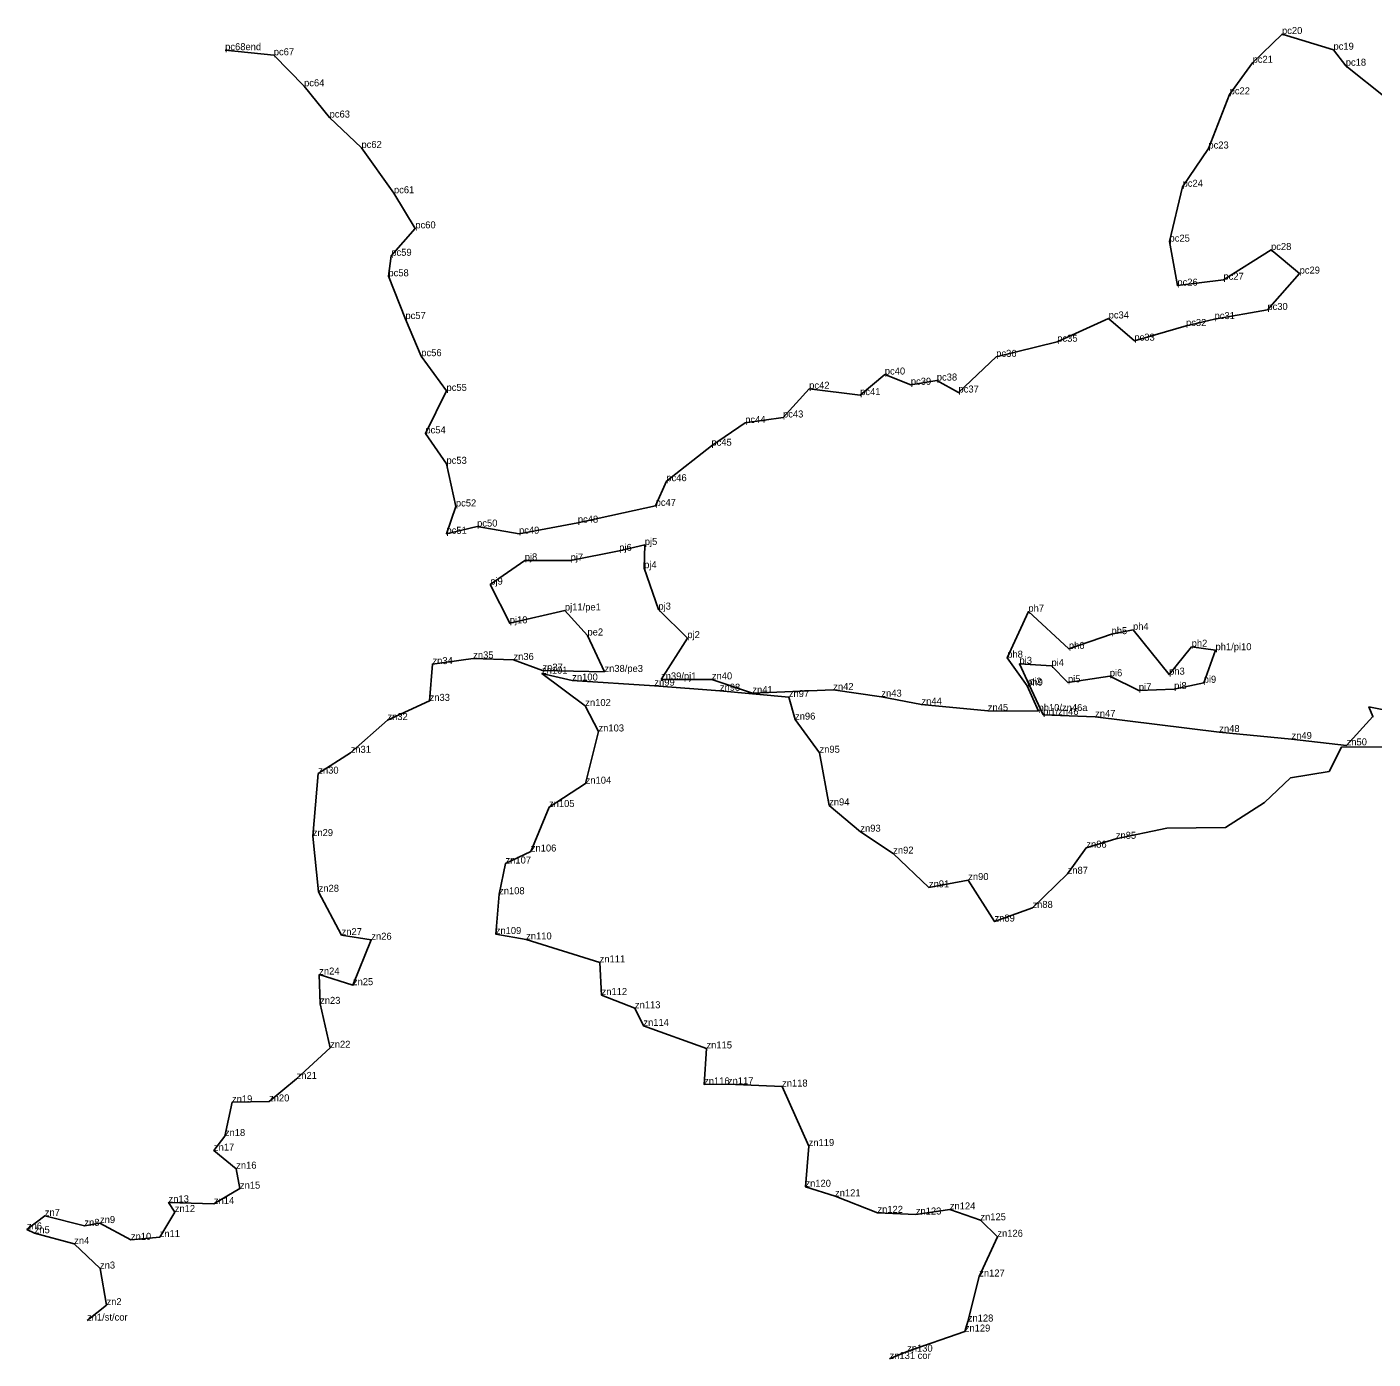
# Model space of a CAD drawing. Extents: x 2072529 to 2267990, y 436423 to 470008.
# Drawn here: x 2230236 to 2231389, y 437912 to 439053 of the extents above; entities that cross this region are included whole.
import ezdxf

# ---------------------------------------------------------------- set-up
doc = ezdxf.new("R2010")
doc.units = 0
doc.layers.add('Level 3', color=7, linetype='Continuous')
doc.layers.add('Old_Level_52', color=7, linetype='Continuous')

msp = doc.modelspace()

# ---------------------------------------------------------------- linework, layer by layer
at = {"layer": 'Level 3'}
for p, q in [((2231310.939, 439047.151), (2231310.939, 439047.151)), ((2230405.831, 439033.328), (2230405.831, 439033.328)), ((2230447.46, 439028.971), (2230447.46, 439028.971)), ((2231355.02, 439033.712), (2231355.02, 439033.712)), ((2231285.762, 439022.487), (2231285.762, 439022.487)), ((2231365.533, 439019.989), (2231365.533, 439019.989)), ((2230473.411, 439002.406), (2230473.411, 439002.406)), ((2231266.087, 438995.494), (2231266.087, 438995.494)), ((2230495.293, 438975.627), (2230495.293, 438975.627)), ((2230522.567, 438949.582), (2230522.567, 438949.582)), ((2231247.897, 438949.098), (2231247.897, 438949.098)), ((2231225.791, 438916.331), (2231225.791, 438916.331)), ((2230550.391, 438910.797), (2230550.391, 438910.797)), ((2230568.692, 438880.673), (2230568.692, 438880.673)), ((2231214.611, 438869.338), (2231214.611, 438869.338)), ((2230548.133, 438857.217), (2230548.133, 438857.217)), ((2231301.537, 438862.206), (2231301.537, 438862.206)), ((2230545.636, 438839.663), (2230545.636, 438839.663)), ((2231221.32, 438831.672), (2231221.32, 438831.672)), ((2231260.743, 438836.686), (2231260.743, 438836.686)), ((2231326.024, 438841.986), (2231326.024, 438841.986)), ((2231298.42, 438810.803), (2231298.42, 438810.803)), ((2230560.209, 438803.028), (2230560.209, 438803.028)), ((2231162.477, 438803.55), (2231162.477, 438803.55)), ((2231228.715, 438797.116), (2231228.715, 438797.116)), ((2231253.174, 438803.008), (2231253.174, 438803.008)), ((2231184.503, 438784.523), (2231184.503, 438784.523)), ((2231118.455, 438783.598), (2231118.455, 438783.598)), ((2230573.781, 438771.245), (2230573.781, 438771.245)), ((2231066.183, 438770.672), (2231066.183, 438770.672)), ((2230970.771, 438755.527), (2230970.771, 438755.527)), ((2231015.31, 438750.373), (2231015.31, 438750.373)), ((2230595.395, 438741.485), (2230595.395, 438741.485)), ((2230906.001, 438743.321), (2230906.001, 438743.321)), ((2230993.066, 438746.762), (2230993.066, 438746.762)), ((2231033.873, 438740.121), (2231033.873, 438740.121)), ((2230949.664, 438737.874), (2230949.664, 438737.874)), ((2230883.589, 438718.737), (2230883.589, 438718.737)), ((2230577.298, 438705.125), (2230577.298, 438705.125)), ((2230851.215, 438714.046), (2230851.215, 438714.046)), ((2230822.259, 438694.53), (2230822.259, 438694.53)), ((2230595.378, 438679.047), (2230595.378, 438679.047)), ((2230783.671, 438664.176), (2230783.671, 438664.176)), ((2230603.451, 438642.538), (2230603.451, 438642.538)), ((2230774.498, 438643.053), (2230774.498, 438643.053)), ((2230621.592, 438625.293), (2230621.592, 438625.293)), ((2230707.866, 438628.604), (2230707.866, 438628.604)), ((2230595.38, 438619.106), (2230595.38, 438619.106)), ((2230657.511, 438619.21), (2230657.511, 438619.21)), ((2230743.307, 438604.473), (2230743.307, 438604.473)), ((2230765.194, 438609.563), (2230765.194, 438609.563)), ((2230662.389, 438596.38), (2230662.389, 438596.38)), ((2230701.659, 438596.151), (2230701.659, 438596.151)), ((2230764.662, 438589.686), (2230764.662, 438589.686)), ((2230632.844, 438575.589), (2230632.844, 438575.589)), ((2230776.862, 438554.192), (2230776.862, 438554.192)), ((2230649.553, 438542.437), (2230649.553, 438542.437)), ((2230696.786, 438553.431), (2230696.786, 438553.431)), ((2231093.706, 438552.451), (2231093.706, 438552.451)), ((2230716.124, 438532.013), (2230716.124, 438532.013)), ((2231164.949, 438533.178), (2231164.949, 438533.178)), ((2231183.359, 438536.86), (2231183.359, 438536.86)), ((2230801.646, 438529.778), (2230801.646, 438529.778)), ((2231128.407, 438520.53), (2231128.407, 438520.53)), ((2231233.56, 438522.426), (2231233.56, 438522.426)), ((2231253.979, 438519.434), (2231253.979, 438519.434)), ((2230618.25, 438512.377), (2230618.25, 438512.377)), ((2230652.739, 438511.054), (2230652.739, 438511.054)), ((2231075.618, 438513.001), (2231075.618, 438513.001)), ((2230583.339, 438507.503), (2230583.339, 438507.503)), ((2230677.154, 438499.344), (2230677.154, 438499.344)), ((2230677.577, 438501.915), (2230677.577, 438501.915)), ((2230730.635, 438500.82), (2230730.635, 438500.82)), ((2231086.1, 438507.739), (2231086.1, 438507.739)), ((2231113.506, 438505.973), (2231113.506, 438505.973)), ((2231163.43, 438497.127), (2231163.43, 438497.127)), ((2231214.241, 438498.484), (2231214.241, 438498.484)), ((2230703.077, 438493.453), (2230703.077, 438493.453)), ((2230773.413, 438489.04), (2230773.413, 438489.04)), ((2230779.099, 438494.344), (2230779.099, 438494.344)), ((2230822.636, 438494.431), (2230822.636, 438494.431)), ((2230926.6, 438485.362), (2230926.6, 438485.362)), ((2231092.731, 438489.038), (2231092.731, 438489.038)), ((2231094.274, 438489.856), (2231094.274, 438489.856)), ((2231127.606, 438491.863), (2231127.606, 438491.863)), ((2231188.302, 438484.985), (2231188.302, 438484.985)), ((2231218.577, 438486.154), (2231218.577, 438486.154)), ((2231243.846, 438491.506), (2231243.846, 438491.506)), ((2230580.917, 438476.025), (2230580.917, 438476.025)), ((2230829.511, 438484.694), (2230829.511, 438484.694)), ((2230857.331, 438482.66), (2230857.331, 438482.66)), ((2230888.561, 438479.289), (2230888.561, 438479.289)), ((2230967.821, 438479.621), (2230967.821, 438479.621)), ((2230714.241, 438471.668), (2230714.241, 438471.668)), ((2231002.165, 438472.775), (2231002.165, 438472.775)), ((2231058.976, 438467.467), (2231058.976, 438467.467)), ((2231102.432, 438467.32), (2231102.432, 438467.32)), ((2231106.33, 438463.945), (2231106.33, 438463.945)), ((2231150.873, 438462.26), (2231150.873, 438462.26)), ((2231388.763, 438462.605), (2231388.763, 438462.605)), ((2230544.811, 438459.575), (2230544.811, 438459.575)), ((2230893.868, 438459.965), (2230893.868, 438459.965)), ((2230725.563, 438449.815), (2230725.563, 438449.815)), ((2231257.201, 438449.319), (2231257.201, 438449.319)), ((2231319.092, 438443.334), (2231319.092, 438443.334)), ((2230513.299, 438431.528), (2230513.299, 438431.528)), ((2230914.834, 438431.593), (2230914.834, 438431.593)), ((2231366.264, 438437.874), (2231366.264, 438437.874)), ((2230485.56, 438413.683), (2230485.56, 438413.683)), ((2230714.565, 438405.115), (2230714.565, 438405.115)), ((2230683.171, 438385.102), (2230683.171, 438385.102)), ((2230923.078, 438386.475), (2230923.078, 438386.475)), ((2230480.817, 438360.197), (2230480.817, 438360.197)), ((2230949.818, 438363.989), (2230949.818, 438363.989)), ((2230667.597, 438346.988), (2230667.597, 438346.988)), ((2231143.341, 438350.29), (2231143.341, 438350.29)), ((2231168.569, 438357.879), (2231168.569, 438357.879)), ((2230645.912, 438336.705), (2230645.912, 438336.705)), ((2230977.955, 438345.227), (2230977.955, 438345.227)), ((2231127.348, 438327.905), (2231127.348, 438327.905)), ((2230485.895, 438312.516), (2230485.895, 438312.516)), ((2231008.552, 438316.283), (2231008.552, 438316.283)), ((2231042.176, 438322.552), (2231042.176, 438322.552)), ((2230640.408, 438310.426), (2230640.408, 438310.426)), ((2231097.19, 438298.687), (2231097.19, 438298.687)), ((2231064.708, 438287.03), (2231064.708, 438287.03)), ((2230505.549, 438275.391), (2230505.549, 438275.391)), ((2230531.006, 438271.455), (2230531.006, 438271.455)), ((2230637.561, 438276.332), (2230637.561, 438276.332)), ((2230663.58, 438271.657), (2230663.58, 438271.657)), ((2230726.563, 438252.057), (2230726.563, 438252.057)), ((2230486.366, 438241.632), (2230486.366, 438241.632)), ((2230515.222, 438232.535), (2230515.222, 438232.535)), ((2230728.203, 438224.109), (2230728.203, 438224.109)), ((2230487.132, 438216.516), (2230487.132, 438216.516)), ((2230756.759, 438212.749), (2230756.759, 438212.749)), ((2230763.994, 438197.68), (2230763.994, 438197.68)), ((2230495.691, 438178.911), (2230495.691, 438178.911)), ((2230818.043, 438178.348), (2230818.043, 438178.348)), ((2230467.018, 438152.256), (2230467.018, 438152.256)), ((2230815.968, 438147.547), (2230815.968, 438147.547)), ((2230836.377, 438147.671), (2230836.377, 438147.671)), ((2230882.768, 438145.682), (2230882.768, 438145.682)), ((2230411.69, 438132.217), (2230411.69, 438132.217)), ((2230443.396, 438132.954), (2230443.396, 438132.954)), ((2230405.568, 438103.302), (2230405.568, 438103.302)), ((2230905.558, 438094.768), (2230905.558, 438094.768)), ((2230396.199, 438090.877), (2230396.199, 438090.877)), ((2230415.261, 438075.336), (2230415.261, 438075.336)), ((2230418.466, 438058.268), (2230418.466, 438058.268)), ((2230902.75, 438059.87), (2230902.75, 438059.87)), ((2230928.135, 438051.731), (2230928.135, 438051.731)), ((2230357.359, 438046.533), (2230357.359, 438046.533)), ((2230362.647, 438038.259), (2230362.647, 438038.259)), ((2230396.169, 438045.119), (2230396.169, 438045.119)), ((2230964.443, 438037.537), (2230964.443, 438037.537)), ((2230997.313, 438036.112), (2230997.313, 438036.112)), ((2231026.441, 438040.43), (2231026.441, 438040.43)), ((2230251.357, 438034.955), (2230251.357, 438034.955)), ((2230285.253, 438026.391), (2230285.253, 438026.391)), ((2230298.62, 438028.753), (2230298.62, 438028.753)), ((2231052.615, 438031.201), (2231052.615, 438031.201)), ((2230236.05, 438023.325), (2230236.05, 438023.325)), ((2230242.646, 438020.093), (2230242.646, 438020.093)), ((2230325.096, 438014.422), (2230325.096, 438014.422)), ((2230349.737, 438016.733), (2230349.737, 438016.733)), ((2231067.164, 438017.056), (2231067.164, 438017.056)), ((2230276.544, 438010.892), (2230276.544, 438010.892)), ((2230298.636, 437989.826), (2230298.636, 437989.826)), ((2231051.606, 437983.008), (2231051.606, 437983.008)), ((2230304.22, 437958.48), (2230304.22, 437958.48)), ((2230287.505, 437945.265), (2230287.505, 437945.265)), ((2231041.838, 437944.457), (2231041.838, 437944.457)), ((2231039.241, 437935.876), (2231039.241, 437935.876)), ((2230974.811, 437912.378), (2230974.811, 437912.378)), ((2230989.871, 437918.676), (2230989.871, 437918.676))]:
    msp.add_line(p, q, dxfattribs=at)
at = {"layer": 'Old_Level_52'}
for points in [[(2231400.682, 438991.914), (2231365.533, 439019.989), (2231355.02, 439033.712), (2231310.939, 439047.151), (2231285.762, 439022.487), (2231266.087, 438995.494), (2231247.897, 438949.098), (2231225.791, 438916.331), (2231214.611, 438869.338), (2231221.32, 438831.672), (2231260.743, 438836.686), (2231301.537, 438862.206), (2231326.024, 438841.986), (2231298.42, 438810.803), (2231253.174, 438803.008), (2231228.715, 438797.116), (2231184.503, 438784.523), (2231162.477, 438803.55), (2231118.455, 438783.598), (2231066.183, 438770.672), (2231033.873, 438740.121), (2231015.31, 438750.373), (2230993.066, 438746.762), (2230970.771, 438755.527), (2230949.664, 438737.874), (2230906.001, 438743.321), (2230883.589, 438718.737), (2230851.215, 438714.046), (2230822.259, 438694.53), (2230783.671, 438664.176), (2230774.498, 438643.053), (2230707.866, 438628.604), (2230657.511, 438619.21), (2230621.592, 438625.293), (2230595.38, 438619.106), (2230603.451, 438642.538), (2230595.378, 438679.047), (2230577.298, 438705.125), (2230595.395, 438741.485), (2230573.781, 438771.245), (2230560.209, 438803.028), (2230545.636, 438839.663), (2230548.133, 438857.217), (2230568.692, 438880.673), (2230550.391, 438910.797), (2230522.567, 438949.582), (2230495.293, 438975.627), (2230473.411, 439002.406), (2230447.46, 439028.971), (2230405.831, 439033.328)], [(2230779.099, 438494.344), (2230801.646, 438529.778), (2230776.862, 438554.192), (2230764.662, 438589.686), (2230765.194, 438609.563), (2230743.307, 438604.473), (2230701.659, 438596.151), (2230662.389, 438596.38), (2230632.844, 438575.589), (2230649.553, 438542.437), (2230696.786, 438553.431), (2230716.124, 438532.013), (2230730.635, 438500.82)], [(2231106.33, 438463.945), (2231094.273, 438489.856), (2231086.1, 438507.739), (2231113.506, 438505.973), (2231127.606, 438491.863), (2231163.43, 438497.127), (2231188.302, 438484.985), (2231218.577, 438486.154), (2231243.846, 438491.506), (2231253.979, 438519.434), (2231233.56, 438522.426), (2231214.241, 438498.484), (2231183.359, 438536.86), (2231164.949, 438533.178), (2231128.407, 438520.53), (2231093.706, 438552.451), (2231075.618, 438513.001), (2231092.73, 438489.038), (2231102.432, 438467.32)], [(2230287.505, 437945.265), (2230304.22, 437958.48), (2230298.636, 437989.826), (2230276.544, 438010.892), (2230242.646, 438020.093), (2230236.05, 438023.325), (2230251.357, 438034.955), (2230285.253, 438026.391), (2230298.62, 438028.753), (2230325.096, 438014.422), (2230349.737, 438016.733), (2230362.647, 438038.259), (2230357.359, 438046.533), (2230396.169, 438045.119), (2230418.466, 438058.268), (2230415.261, 438075.336), (2230396.199, 438090.877), (2230405.568, 438103.302), (2230411.69, 438132.217), (2230443.396, 438132.954), (2230467.018, 438152.256), (2230495.691, 438178.911), (2230487.132, 438216.516), (2230486.366, 438241.632), (2230515.222, 438232.535), (2230531.006, 438271.455), (2230505.549, 438275.391), (2230485.895, 438312.516), (2230480.817, 438360.197), (2230485.56, 438413.683), (2230513.299, 438431.528), (2230544.811, 438459.575), (2230580.917, 438476.025), (2230583.339, 438507.503), (2230618.25, 438512.377), (2230652.739, 438511.054), (2230677.577, 438501.915), (2230730.635, 438500.82)], [(2230773.413, 438489.04), (2230703.077, 438493.453), (2230677.154, 438499.344), (2230714.241, 438471.668), (2230725.563, 438449.815), (2230714.565, 438405.115), (2230683.171, 438385.102), (2230667.597, 438346.988), (2230645.912, 438336.705), (2230640.408, 438310.426), (2230637.561, 438276.332), (2230663.58, 438271.657), (2230726.563, 438252.057), (2230728.203, 438224.109), (2230756.759, 438212.749), (2230763.994, 438197.68), (2230818.043, 438178.348), (2230815.968, 438147.547), (2230836.377, 438147.671), (2230882.768, 438145.682), (2230905.558, 438094.768), (2230902.75, 438059.87), (2230928.135, 438051.731), (2230964.443, 438037.537), (2230997.313, 438036.112), (2231026.441, 438040.43), (2231052.615, 438031.201), (2231067.164, 438017.056), (2231051.606, 437983.008), (2231041.838, 437944.457), (2231039.241, 437935.876), (2230989.871, 437918.676), (2230974.811, 437912.378)], [(2231168.569, 438357.879), (2231143.341, 438350.29), (2231127.348, 438327.905), (2231097.19, 438298.687), (2231064.708, 438287.03), (2231042.176, 438322.552), (2231008.552, 438316.283), (2230977.955, 438345.227), (2230949.818, 438363.989), (2230923.078, 438386.475), (2230914.834, 438431.593), (2230893.868, 438459.965), (2230888.532, 438479.288), (2230829.511, 438484.694), (2230773.413, 438489.04)], [(2230779.099, 438494.344), (2230822.636, 438494.431), (2230857.331, 438482.66), (2230926.6, 438485.362), (2230967.821, 438479.621), (2231002.165, 438472.775), (2231058.976, 438467.467), (2231102.432, 438467.32)], [(2231106.33, 438463.945), (2231150.873, 438462.26), (2231257.201, 438449.319), (2231319.092, 438443.334), (2231366.264, 438437.874), (2231388.763, 438462.605)], [(2231407.746, 438466.318), (2231385.301, 438470.85), (2231388.763, 438462.605), (2231389.195, 438462.745)], [(2231168.569, 438357.879), (2231212.348, 438367.123), (2231262.574, 438367.521), (2231295.835, 438388.926), (2231318.259, 438409.984), (2231351.285, 438415.525), (2231362.005, 438436.45), (2231401.873, 438436.73)]]:
    msp.add_lwpolyline(points, dxfattribs=at)

# ---------------------------------------------------------------- texts
for s, p in [('pc20', (2231310.939, 439047.151)), ('pc68end', (2230405.831, 439033.328)), ('pc19', (2231355.02, 439033.712)), ('pc67', (2230447.46, 439028.971)), ('pc21', (2231285.762, 439022.487)), ('pc18', (2231365.533, 439019.989)), ('pc64', (2230473.411, 439002.406)), ('pc22', (2231266.087, 438995.494)), ('pc63', (2230495.293, 438975.627)), ('pc62', (2230522.567, 438949.582)), ('pc23', (2231247.897, 438949.098)), ('pc61', (2230550.391, 438910.797)), ('pc24', (2231225.791, 438916.331)), ('pc60', (2230568.692, 438880.673)), ('pc25', (2231214.611, 438869.338)), ('pc28', (2231301.537, 438862.206)), ('pc59', (2230548.133, 438857.217)), ('pc58', (2230545.636, 438839.663)), ('pc27', (2231260.743, 438836.686)), ('pc29', (2231326.024, 438841.986)), ('pc26', (2231221.32, 438831.672)), ('pc57', (2230560.209, 438803.028)), ('pc34', (2231162.477, 438803.55)), ('pc31', (2231253.174, 438803.008)), ('pc30', (2231298.42, 438810.803)), ('pc32', (2231228.715, 438797.116)), ('pc35', (2231118.455, 438783.598)), ('pc33', (2231184.503, 438784.523)), ('pc56', (2230573.781, 438771.245)), ('pc36', (2231066.183, 438770.672)), ('pc40', (2230970.771, 438755.527)), ('pc39', (2230993.066, 438746.762)), ('pc38', (2231015.31, 438750.373)), ('pc55', (2230595.395, 438741.485)), ('pc42', (2230906.001, 438743.321)), ('pc41', (2230949.664, 438737.874)), ('pc37', (2231033.873, 438740.121)), ('pc44', (2230851.215, 438714.046)), ('pc43', (2230883.589, 438718.737)), ('pc54', (2230577.298, 438705.125)), ('pc45', (2230822.259, 438694.53)), ('pc53', (2230595.378, 438679.047)), ('pc46', (2230783.671, 438664.176)), ('pc52', (2230603.451, 438642.538)), ('pc47', (2230774.498, 438643.053)), ('pc48', (2230707.866, 438628.604)), ('pc51', (2230595.38, 438619.106)), ('pc50', (2230621.592, 438625.293)), ('pc49', (2230657.511, 438619.21)), ('pj5', (2230765.194, 438609.563)), ('pj8', (2230662.389, 438596.38)), ('pj7', (2230701.659, 438596.151)), ('pj6', (2230743.307, 438604.473)), ('pj4', (2230764.662, 438589.686)), ('pj9', (2230632.844, 438575.589)), ('pj11/pe1', (2230696.786, 438553.431)), ('pj3', (2230776.862, 438554.192)), ('ph7', (2231093.706, 438552.451)), ('pj10', (2230649.553, 438542.437)), ('ph4', (2231183.359, 438536.86)), ('pe2', (2230716.124, 438532.013)), ('pj2', (2230801.646, 438529.778)), ('ph5', (2231164.949, 438533.178)), ('ph8', (2231075.618, 438513.001)), ('ph6', (2231128.407, 438520.53)), ('ph2', (2231233.56, 438522.426)), ('ph1/pi10', (2231253.979, 438519.434)), ('zn34', (2230583.339, 438507.503)), ('zn35', (2230618.25, 438512.377)), ('zn36', (2230652.739, 438511.054)), ('zn37', (2230677.577, 438501.915)), ('pi3', (2231086.1, 438507.739)), ('pi4', (2231113.506, 438505.973)), ('zn101', (2230677.154, 438499.344)), ('zn100', (2230703.077, 438493.453)), ('zn38/pe3', (2230730.635, 438500.82)), ('zn39/pj1', (2230779.099, 438494.344)), ('zn40', (2230822.636, 438494.431)), ('pi5', (2231127.606, 438491.863)), ('pi6', (2231163.43, 438497.127)), ('ph3', (2231214.241, 438498.484)), ('pi9', (2231243.846, 438491.506)), ('zn99', (2230773.413, 438489.04)), ('zn98', (2230829.511, 438484.694)), ('zn41', (2230857.331, 438482.66)), ('zn97', (2230888.532, 438479.288)), ('zn42', (2230926.6, 438485.362)), ('zn43', (2230967.821, 438479.621)), ('ph9', (2231092.73, 438489.038)), ('pi2', (2231094.273, 438489.856)), ('pi7', (2231188.302, 438484.985)), ('pi8', (2231218.577, 438486.154)), ('zn33', (2230580.917, 438476.025)), ('zn102', (2230714.241, 438471.668)), ('zn44', (2231002.165, 438472.775)), ('zn45', (2231058.976, 438467.467)), ('ph10/zn46a', (2231102.432, 438467.32)), ('zn32', (2230544.811, 438459.575)), ('zn96', (2230893.868, 438459.965)), ('pi1/zn46', (2231106.33, 438463.945)), ('zn47', (2231150.873, 438462.26)), ('zn103', (2230725.563, 438449.815)), ('zn48', (2231257.201, 438449.319)), ('zn49', (2231319.092, 438443.334)), ('zn50', (2231366.264, 438437.874)), ('zn31', (2230513.299, 438431.528)), ('zn95', (2230914.834, 438431.593)), ('zn30', (2230485.56, 438413.683)), ('zn104', (2230714.565, 438405.115)), ('zn94', (2230923.078, 438386.475)), ('zn105', (2230683.171, 438385.102)), ('zn93', (2230949.818, 438363.989)), ('zn29', (2230480.817, 438360.197)), ('zn85', (2231168.569, 438357.879)), ('zn106', (2230667.597, 438346.988)), ('zn92', (2230977.955, 438345.227)), ('zn86', (2231143.341, 438350.29)), ('zn107', (2230645.912, 438336.705)), ('zn90', (2231042.176, 438322.552)), ('zn87', (2231127.348, 438327.905)), ('zn28', (2230485.895, 438312.516)), ('zn108', (2230640.408, 438310.426)), ('zn91', (2231008.552, 438316.283)), ('zn88', (2231097.19, 438298.687)), ('zn89', (2231064.708, 438287.03)), ('zn27', (2230505.549, 438275.391)), ('zn26', (2230531.006, 438271.455)), ('zn109', (2230637.561, 438276.332)), ('zn110', (2230663.58, 438271.657)), ('zn111', (2230726.563, 438252.057)), ('zn24', (2230486.366, 438241.632)), ('zn25', (2230515.222, 438232.535)), ('zn23', (2230487.132, 438216.516)), ('zn112', (2230728.203, 438224.109)), ('zn113', (2230756.759, 438212.749)), ('zn114', (2230763.994, 438197.68)), ('zn22', (2230495.691, 438178.911)), ('zn115', (2230818.043, 438178.348)), ('zn21', (2230467.018, 438152.256)), ('zn116', (2230815.968, 438147.547)), ('zn117', (2230836.377, 438147.671)), ('zn118', (2230882.768, 438145.682)), ('zn20', (2230443.396, 438132.954)), ('zn19', (2230411.69, 438132.217)), ('zn18', (2230405.568, 438103.302)), ('zn17', (2230396.199, 438090.877)), ('zn119', (2230905.558, 438094.768)), ('zn16', (2230415.261, 438075.336)), ('zn15', (2230418.466, 438058.268)), ('zn120', (2230902.75, 438059.87)), ('zn13', (2230357.359, 438046.533)), ('zn14', (2230396.169, 438045.119)), ('zn121', (2230928.135, 438051.731)), ('zn7', (2230251.357, 438034.955)), ('zn12', (2230362.647, 438038.259)), ('zn122', (2230964.443, 438037.537)), ('zn123', (2230997.313, 438036.112)), ('zn124', (2231026.441, 438040.43)), ('zn125', (2231052.615, 438031.201)), ('zn6', (2230236.05, 438023.325)), ('zn5', (2230242.646, 438020.093)), ('zn8', (2230285.253, 438026.391)), ('zn9', (2230298.62, 438028.753)), ('zn4', (2230276.544, 438010.892)), ('zn10', (2230325.096, 438014.422)), ('zn11', (2230349.737, 438016.733)), ('zn126', (2231067.164, 438017.056)), ('zn3', (2230298.636, 437989.826)), ('zn127', (2231051.606, 437983.008)), ('zn2', (2230304.22, 437958.48)), ('zn1/st/cor', (2230287.505, 437945.265)), ('zn128', (2231041.838, 437944.457)), ('zn129', (2231039.241, 437935.876)), ('zn130', (2230989.871, 437918.676)), ('zn131 cor', (2230974.811, 437912.378))]:
    msp.add_text(s, height=6).set_placement(p)

doc.saveas('drawing.dxf')
